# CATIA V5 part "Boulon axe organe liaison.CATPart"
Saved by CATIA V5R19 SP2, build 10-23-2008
Part number: Boulon axe organe liaison
Bounding box of the stored display mesh (mm): x -4.498 to 4.498, y -4.5 to 4.5, z 0 to 5
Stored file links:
  C:\Users\Romain\Documents\IFMA\2A\cours\S3\Projet CFAO-IAO\CFAO\Catia\Organe de fixation\Boulon axe organe liaison.CATPart
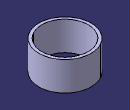
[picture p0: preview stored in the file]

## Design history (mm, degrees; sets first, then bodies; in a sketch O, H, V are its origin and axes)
Body1 (main body)
  Sketch1 on yz-plane, origin (0, 0, 0), H (0, 1, 0), V (0, 0, 1)
    line L1 (4, 5) -> (4.5, 5)
    line L2 (4.5, 5) -> (4.5, 0)
    line L3 (4.5, 0) -> (4, 0)
    line L4 (4, 0) -> (4, 5)
    length L2 = 5
    length L1 = 0.5
    distance L4 V = 4
    distance L3 H = 0
    horizontal: L1 H, L3 H
    vertical: L2 V, L4 V
  Shaft1: profile Sketch1, axis Sketch1.V, angle 360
